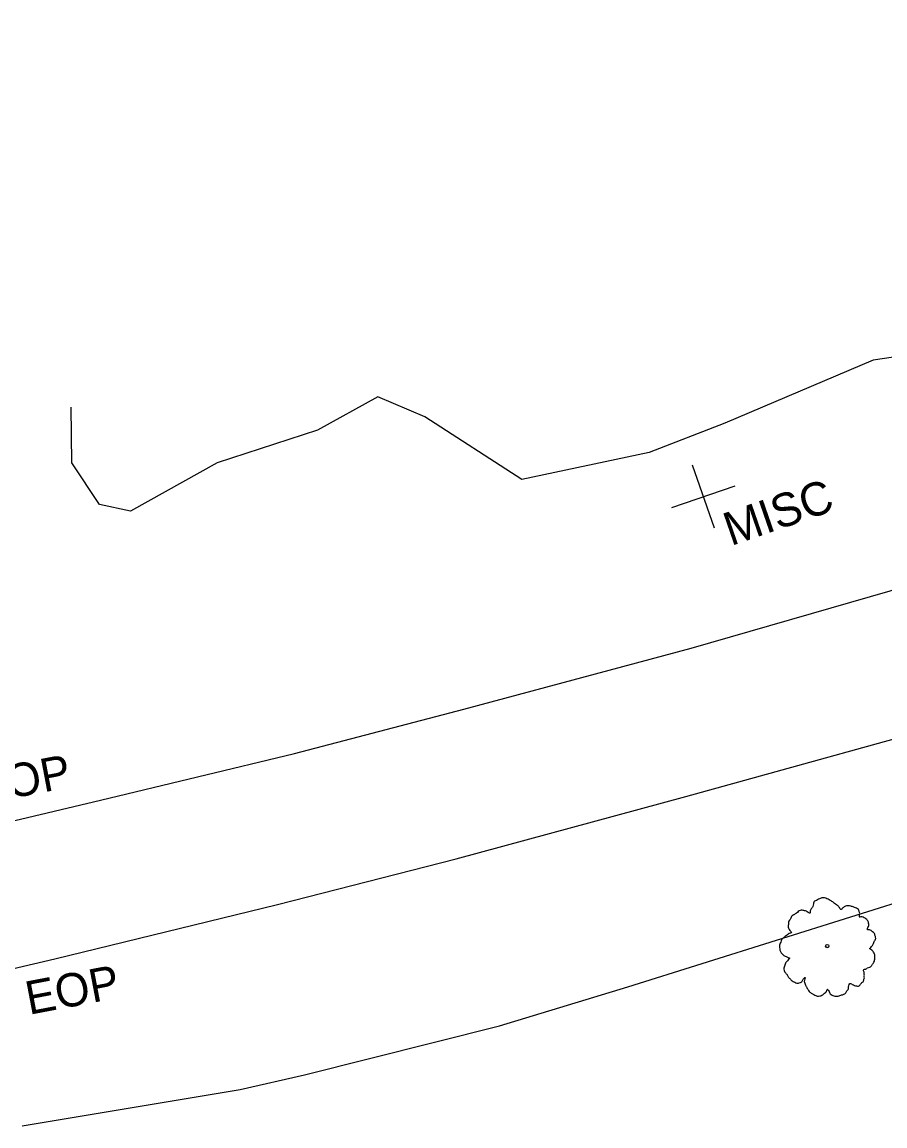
# Model space of a CAD drawing. Extents: x 2076109 to 2080761, y 592812 to 596750.
# Drawn here: x 2076413.9 to 2076543.2, y 595332.3 to 595497.8 of the extents above; entities that cross this region are included whole.
import ezdxf

# ---------------------------------------------------------------- set-up
doc = ezdxf.new("R2010")
doc.units = 0
for name, color, linetype in [('RD_EX_Fence_Other', 7, 'Continuous'), ('RD_EX_Misc', 7, 'Continuous'), ('RD_EX_Misc_txCode', 7, 'Continuous'), ('RD_EX_Road', 7, 'Continuous'), ('RD_EX_Road_txCode', 7, 'Continuous'), ('RD_EX_VEG', 7, 'Continuous')]:
    doc.layers.add(name, color=color, linetype=linetype)

msp = doc.modelspace()

# ---------------------------------------------------------------- linework, layer by layer
at = {"layer": 'RD_EX_Fence_Other'}
msp.add_lwpolyline([(2076413.91, 595332.33), (2076446.57, 595337.77), (2076456.21, 595339.99), (2076485.43, 595347.34), (2076504.69, 595353.19), (2076571.51, 595374.19), (2076584.94, 595364.39)], dxfattribs=at)
msp.add_lwpolyline([(2076413.91, 595332.33), (2076446.57, 595337.77), (2076456.21, 595339.99), (2076485.43, 595347.34), (2076504.69, 595353.19), (2076571.51, 595374.19), (2076584.94, 595364.39)], dxfattribs=at)
at = {"layer": 'RD_EX_Misc'}
for p, q in [((2076517.66, 595421.97), (2076514.39, 595431.42)), ((2076517.66, 595421.97), (2076514.39, 595431.42)), ((2076511.3, 595425.06), (2076520.75, 595428.33)), ((2076511.3, 595425.06), (2076520.75, 595428.33))]:
    msp.add_line(p, q, dxfattribs=at)
at = {"layer": 'RD_EX_Road'}
for points in [[(2076404.77, 595376.23), (2076425.66, 595381.19), (2076454.7, 595388.18), (2076480.11, 595394.8), (2076514.19, 595403.96), (2076543.98, 595412.58), (2076583.19, 595424.9), (2076620.49, 595437.36), (2076654.29, 595449.62), (2076691.86, 595464.03), (2076699.44, 595467.03), (2076707.59, 595470.49)], [(2076404.77, 595376.23), (2076425.66, 595381.19), (2076454.7, 595388.18), (2076480.11, 595394.8), (2076514.19, 595403.96), (2076543.98, 595412.58), (2076583.19, 595424.9), (2076620.49, 595437.36), (2076654.29, 595449.62), (2076691.86, 595464.03), (2076699.44, 595467.03), (2076707.59, 595470.49)], [(2076409.15, 595355.14), (2076418.82, 595357.38), (2076452.18, 595365.54), (2076478.97, 595372.37), (2076513.39, 595381.71), (2076544.59, 595390.37), (2076569.72, 595398.06), (2076592.75, 595405.46), (2076641.5, 595422.06), (2076663.28, 595429.78), (2076676.52, 595432.55), (2076693.19, 595435.72), (2076711.91, 595438.8), (2076719.56, 595439.35)], [(2076409.15, 595355.14), (2076418.82, 595357.38), (2076452.18, 595365.54), (2076478.97, 595372.37), (2076513.39, 595381.71), (2076544.59, 595390.37), (2076569.72, 595398.06), (2076592.75, 595405.46), (2076641.5, 595422.06), (2076663.28, 595429.78), (2076676.52, 595432.55), (2076693.19, 595435.72), (2076711.91, 595438.8), (2076719.56, 595439.35)]]:
    msp.add_lwpolyline(points, dxfattribs=at)
at = {"layer": 'RD_EX_VEG'}
msp.add_lwpolyline([(2076721.44, 595497.84), (2076686.85, 595487.97), (2076651.97, 595472.98), (2076631.79, 595471.84), (2076615.46, 595464.14), (2076596.55, 595455.13), (2076574.34, 595452), (2076541.43, 595447.14), (2076519.2, 595437.7), (2076507.89, 595433.3), (2076488.78, 595429.26), (2076474.26, 595438.65), (2076467.23, 595441.67), (2076458.17, 595436.65), (2076443.11, 595431.74), (2076430.14, 595424.51), (2076425.47, 595425.53), (2076421.37, 595431.78), (2076421.26, 595440.12)], dxfattribs=at)
msp.add_lwpolyline([(2076721.44, 595497.84), (2076686.85, 595487.97), (2076651.97, 595472.98), (2076631.79, 595471.84), (2076615.46, 595464.14), (2076596.55, 595455.13), (2076574.34, 595452), (2076541.43, 595447.14), (2076519.2, 595437.7), (2076507.89, 595433.3), (2076488.78, 595429.26), (2076474.26, 595438.65), (2076467.23, 595441.67), (2076458.17, 595436.65), (2076443.11, 595431.74), (2076430.14, 595424.51), (2076425.47, 595425.53), (2076421.37, 595431.78), (2076421.26, 595440.12)], dxfattribs=at)
for centre, radius in [((2076534.58, 595359.31), 0.25), ((2076534.58, 595359.31), 0.25), ((2076534.56, 595359.31), 0.0001), ((2076534.56, 595359.31), 0.0001)]:
    msp.add_circle(centre, radius, dxfattribs=at)
for points in [[(2076539.33, 595364.69), (2076539.12, 595364.9), (2076538.8, 595365.04), (2076538.55, 595365.12), (2076538.33, 595365.21), (2076538.09, 595365.28), (2076537.75, 595365.34), (2076537.45, 595365.34), (2076537.19, 595365.23), (2076537.01, 595365.09), (2076536.79, 595364.91), (2076536.68, 595364.78), (2076536.57, 595364.84), (2076536.47, 595364.95), (2076536.33, 595365.17), (2076536.14, 595365.34), (2076535.95, 595365.5), (2076535.66, 595365.7), (2076535.4, 595365.93), (2076535.16, 595366.07), (2076534.88, 595366.24), (2076534.51, 595366.39), (2076534.16, 595366.52), (2076533.77, 595366.53), (2076533.27, 595366.33), (2076532.95, 595366.14), (2076532.68, 595366.05), (2076532.5, 595365.61), (2076532.41, 595365.23), (2076532.3, 595365.06), (2076532.08, 595364.69), (2076532.01, 595364.45), (2076531.97, 595364.22), (2076531.9, 595364.25), (2076531.58, 595364.45), (2076531.29, 595364.57), (2076530.82, 595364.67), (2076530.5, 595364.65), (2076530.22, 595364.47), (2076529.97, 595364.22), (2076529.76, 595364.13), (2076529.53, 595363.97), (2076529.46, 595363.93), (2076529.21, 595363.71), (2076529, 595363.3), (2076528.79, 595363.02), (2076528.74, 595362.77), (2076528.74, 595362.54), (2076528.71, 595362.23), (2076528.87, 595361.8), (2076529.05, 595361.52), (2076529.19, 595361.37), (2076528.73, 595361.1), (2076528.47, 595360.87), (2076528.11, 595360.64), (2076528.07, 595360.59), (2076527.72, 595360.26), (2076527.62, 595359.91), (2076527.44, 595359.58), (2076527.43, 595359.29), (2076527.44, 595358.89), (2076527.54, 595358.51), (2076527.84, 595358.09), (2076528.16, 595357.85), (2076528.71, 595357.61), (2076528.95, 595357.5), (2076528.82, 595357.39), (2076528.6, 595357.08), (2076528.32, 595356.76), (2076528.23, 595356.42), (2076528.12, 595356.14), (2076528.08, 595355.85), (2076528.18, 595355.47), (2076528.43, 595355.16), (2076528.66, 595354.77), (2076528.96, 595354.42), (2076529.32, 595354.08), (2076529.87, 595353.8), (2076530.16, 595353.72), (2076530.35, 595353.79), (2076530.75, 595353.94), (2076530.86, 595354.15), (2076531.26, 595354.59), (2076531.23, 595354.39), (2076531.13, 595354.01), (2076531.32, 595353.46), (2076531.51, 595353.07), (2076531.78, 595352.64), (2076531.96, 595352.39), (2076532.37, 595352.14), (2076532.7, 595351.96), (2076533.07, 595351.81), (2076533.47, 595351.82), (2076533.78, 595351.92), (2076534, 595352.1), (2076534.3, 595352.33), (2076534.45, 595352.44)], [(2076539.33, 595364.69), (2076539.12, 595364.9), (2076538.8, 595365.04), (2076538.55, 595365.12), (2076538.33, 595365.21), (2076538.09, 595365.28), (2076537.75, 595365.34), (2076537.45, 595365.34), (2076537.19, 595365.23), (2076537.01, 595365.09), (2076536.79, 595364.91), (2076536.68, 595364.78), (2076536.57, 595364.84), (2076536.47, 595364.95), (2076536.33, 595365.17), (2076536.14, 595365.34), (2076535.95, 595365.5), (2076535.66, 595365.7), (2076535.4, 595365.93), (2076535.16, 595366.07), (2076534.88, 595366.24), (2076534.51, 595366.39), (2076534.16, 595366.52), (2076533.77, 595366.53), (2076533.27, 595366.33), (2076532.95, 595366.14), (2076532.68, 595366.05), (2076532.5, 595365.61), (2076532.41, 595365.23), (2076532.3, 595365.06), (2076532.08, 595364.69), (2076532.01, 595364.45), (2076531.97, 595364.22), (2076531.9, 595364.25), (2076531.58, 595364.45), (2076531.29, 595364.57), (2076530.82, 595364.67), (2076530.5, 595364.65), (2076530.22, 595364.47), (2076529.97, 595364.22), (2076529.76, 595364.13), (2076529.53, 595363.97), (2076529.46, 595363.93), (2076529.21, 595363.71), (2076529, 595363.3), (2076528.79, 595363.02), (2076528.74, 595362.77), (2076528.74, 595362.54), (2076528.71, 595362.23), (2076528.87, 595361.8), (2076529.05, 595361.52), (2076529.19, 595361.37), (2076528.73, 595361.1), (2076528.47, 595360.87), (2076528.11, 595360.64), (2076528.07, 595360.59), (2076527.72, 595360.26), (2076527.62, 595359.91), (2076527.44, 595359.58), (2076527.43, 595359.29), (2076527.44, 595358.89), (2076527.54, 595358.51), (2076527.84, 595358.09), (2076528.16, 595357.85), (2076528.71, 595357.61), (2076528.95, 595357.5), (2076528.82, 595357.39), (2076528.6, 595357.08), (2076528.32, 595356.76), (2076528.23, 595356.42), (2076528.12, 595356.14), (2076528.08, 595355.85), (2076528.18, 595355.47), (2076528.43, 595355.16), (2076528.66, 595354.77), (2076528.96, 595354.42), (2076529.32, 595354.08), (2076529.87, 595353.8), (2076530.16, 595353.72), (2076530.35, 595353.79), (2076530.75, 595353.94), (2076530.86, 595354.15), (2076531.26, 595354.59), (2076531.23, 595354.39), (2076531.13, 595354.01), (2076531.32, 595353.46), (2076531.51, 595353.07), (2076531.78, 595352.64), (2076531.96, 595352.39), (2076532.37, 595352.14), (2076532.7, 595351.96), (2076533.07, 595351.81), (2076533.47, 595351.82), (2076533.78, 595351.92), (2076534, 595352.1), (2076534.3, 595352.33), (2076534.45, 595352.44)], [(2076534.45, 595352.44), (2076534.51, 595352.62), (2076534.63, 595352.84), (2076534.67, 595352.77), (2076534.77, 595352.62), (2076534.9, 595352.35), (2076535.02, 595352.14), (2076535.29, 595351.95), (2076535.56, 595351.85), (2076536.08, 595351.77), (2076536.6, 595351.95), (2076537.07, 595352.08), (2076537.34, 595352.28), (2076537.44, 595352.48), (2076537.75, 595352.88), (2076537.76, 595353.2), (2076537.8, 595353.33), (2076537.98, 595353.7), (2076538.07, 595353.69), (2076538.32, 595353.55), (2076538.68, 595353.4), (2076538.97, 595353.32), (2076539.26, 595353.3), (2076539.46, 595353.43), (2076539.7, 595353.75), (2076540, 595354.02), (2076540.04, 595354.18), (2076540.06, 595354.36), (2076540.13, 595354.56), (2076540.11, 595354.77), (2076540.13, 595354.95), (2076540.12, 595355.09), (2076540.12, 595355.29), (2076540.07, 595355.5), (2076539.99, 595355.63), (2076540.05, 595355.78), (2076540.29, 595355.83), (2076540.4, 595355.88), (2076540.56, 595356.03), (2076540.96, 595356.15), (2076541.26, 595356.42), (2076541.49, 595356.78), (2076541.63, 595357.02), (2076541.7, 595357.33), (2076541.71, 595357.65), (2076541.72, 595357.86), (2076541.67, 595358.07), (2076541.51, 595358.38), (2076541.35, 595358.58), (2076541.08, 595358.8), (2076540.96, 595358.97), (2076541.01, 595358.99), (2076541.11, 595359.11), (2076541.29, 595359.32), (2076541.52, 595359.71), (2076541.73, 595360.19), (2076541.75, 595360.21), (2076541.83, 595360.46), (2076541.79, 595360.76), (2076541.72, 595360.95), (2076541.65, 595361.17), (2076541.48, 595361.35), (2076541.25, 595361.55), (2076541.01, 595361.69), (2076540.79, 595361.74), (2076540.58, 595361.76), (2076540.62, 595361.92), (2076540.73, 595362.22), (2076540.79, 595362.36), (2076540.79, 595362.59), (2076540.75, 595362.89), (2076540.49, 595363.28), (2076539.96, 595363.62), (2076539.61, 595363.67), (2076539.38, 595363.63), (2076539.42, 595363.76), (2076539.4, 595364.04), (2076539.44, 595364.24), (2076539.38, 595364.45), (2076539.33, 595364.62), (2076539.29, 595364.72)], [(2076534.45, 595352.44), (2076534.51, 595352.62), (2076534.63, 595352.84), (2076534.67, 595352.77), (2076534.77, 595352.62), (2076534.9, 595352.35), (2076535.02, 595352.14), (2076535.29, 595351.95), (2076535.56, 595351.85), (2076536.08, 595351.77), (2076536.6, 595351.95), (2076537.07, 595352.08), (2076537.34, 595352.28), (2076537.44, 595352.48), (2076537.75, 595352.88), (2076537.76, 595353.2), (2076537.8, 595353.33), (2076537.98, 595353.7), (2076538.07, 595353.69), (2076538.32, 595353.55), (2076538.68, 595353.4), (2076538.97, 595353.32), (2076539.26, 595353.3), (2076539.46, 595353.43), (2076539.7, 595353.75), (2076540, 595354.02), (2076540.04, 595354.18), (2076540.06, 595354.36), (2076540.13, 595354.56), (2076540.11, 595354.77), (2076540.13, 595354.95), (2076540.12, 595355.09), (2076540.12, 595355.29), (2076540.07, 595355.5), (2076539.99, 595355.63), (2076540.05, 595355.78), (2076540.29, 595355.83), (2076540.4, 595355.88), (2076540.56, 595356.03), (2076540.96, 595356.15), (2076541.26, 595356.42), (2076541.49, 595356.78), (2076541.63, 595357.02), (2076541.7, 595357.33), (2076541.71, 595357.65), (2076541.72, 595357.86), (2076541.67, 595358.07), (2076541.51, 595358.38), (2076541.35, 595358.58), (2076541.08, 595358.8), (2076540.96, 595358.97), (2076541.01, 595358.99), (2076541.11, 595359.11), (2076541.29, 595359.32), (2076541.52, 595359.71), (2076541.73, 595360.19), (2076541.75, 595360.21), (2076541.83, 595360.46), (2076541.79, 595360.76), (2076541.72, 595360.95), (2076541.65, 595361.17), (2076541.48, 595361.35), (2076541.25, 595361.55), (2076541.01, 595361.69), (2076540.79, 595361.74), (2076540.58, 595361.76), (2076540.62, 595361.92), (2076540.73, 595362.22), (2076540.79, 595362.36), (2076540.79, 595362.59), (2076540.75, 595362.89), (2076540.49, 595363.28), (2076539.96, 595363.62), (2076539.61, 595363.67), (2076539.38, 595363.63), (2076539.42, 595363.76), (2076539.4, 595364.04), (2076539.44, 595364.24), (2076539.38, 595364.45), (2076539.33, 595364.62), (2076539.29, 595364.72)]]:
    msp.add_spline(points, degree=3, dxfattribs=at)

# ---------------------------------------------------------------- texts
at = {"layer": 'RD_EX_Misc_txCode'}
msp.add_text(' MISC', height=5, rotation=19.0788, dxfattribs=at).set_placement((2076518.37, 595418.65))
msp.add_text(' MISC', height=5, rotation=19.0788, dxfattribs=at).set_placement((2076518.37, 595418.65))
at = {"layer": 'RD_EX_Road_txCode'}
for p in [(2076407.64, 595380.54), (2076407.64, 595380.54), (2076414.93, 595348.98), (2076414.93, 595348.98)]:
    msp.add_text('EOP', height=5, rotation=10.7925, dxfattribs=at).set_placement(p)

doc.saveas('drawing.dxf')
